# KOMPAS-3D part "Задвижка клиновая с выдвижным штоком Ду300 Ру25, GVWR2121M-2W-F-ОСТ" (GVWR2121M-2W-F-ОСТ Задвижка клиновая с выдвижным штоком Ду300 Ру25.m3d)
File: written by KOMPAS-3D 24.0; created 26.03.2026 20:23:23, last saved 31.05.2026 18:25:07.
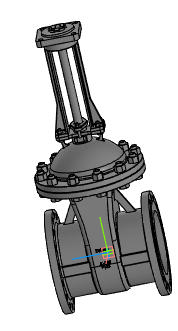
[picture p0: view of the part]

Document properties: Автор: R2D2; Полное имя файла: E:\Работа\Зайцев\GVWR2121M-2W-F-ОСТ Задвижка клиновая 30с964нж DN.ru Ду50-300 Ру25\исходные материалы\DN300\DN300\GVWR2121M-2W-F-ОСТ Задвижка клиновая с выдвижным штоком Ду300 Ру25.m3d

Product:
- Part/product: Задвижка клиновая с выдвижным штоком Ду300 Ру25  | designation GVWR2121M-2W-F-ОСТ
    Масса: 270
    Раздел спецификации: Прочие изделия
    Примечание: D040-07881

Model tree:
1. Операция без истории:1

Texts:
  GVWR2121M-2W-F-ОСТ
